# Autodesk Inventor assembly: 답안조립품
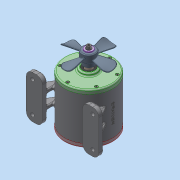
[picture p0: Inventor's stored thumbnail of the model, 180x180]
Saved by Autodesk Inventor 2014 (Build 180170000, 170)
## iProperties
Created: 2024-02
Part Number: 답안조립품
Document SubType Name: Assembly
Designer: dg
Author: dg
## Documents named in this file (20)
- C:\Users\dg\Desktop\640204V1005\답안조립품.iam
- C:\Users\dg\Desktop\640204V1005\본체.ipt
- C:\Users\dg\Desktop\640204V1005\가변스프링.ipt
- C:\Users\dg\Desktop\640204V1005\부시.ipt
- C:\Users\dg\Desktop\640204V1005\슬라이더.ipt
- C:\Users\dg\Desktop\640204V1005\뒷커버.ipt
- C:\Users\dg\Desktop\640204V1005\메인 기어 축.ipt
- C:\Users\dg\Desktop\640204V1005\베어링 608.ipt
- C:\Users\dg\Desktop\640204V1005\베어링 6903.ipt
- C:\Users\dg\Desktop\640204V1005\서브 기어 축.ipt
- C:\Users\dg\Desktop\640204V1005\앞커버.ipt
- C:\Users\dg\Desktop\640204V1005\오일 실 8 22 7.ipt
- C:\Users\dg\Desktop\640204V1005\육각 소켓 머리 볼트 M4 x 12.ipt
- C:\Users\dg\Desktop\640204V1005\오일 실 17 30 8.ipt
- C:\Users\dg\Desktop\640204V1005\키 5 x 5 x 24.ipt
- C:\Users\dg\Desktop\640204V1005\스프링 와셔 M6.ipt
- C:\Users\dg\Desktop\640204V1005\앤드 캡.ipt
- C:\Users\dg\Desktop\640204V1005\육각 소켓 머리 볼트 M6 x 12.ipt
- C:\Users\dg\Desktop\640204V1005\팬날개.ipt
- 팬날개.ipt
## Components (1 placed, 1 different names)
1. 가변스프링:1
